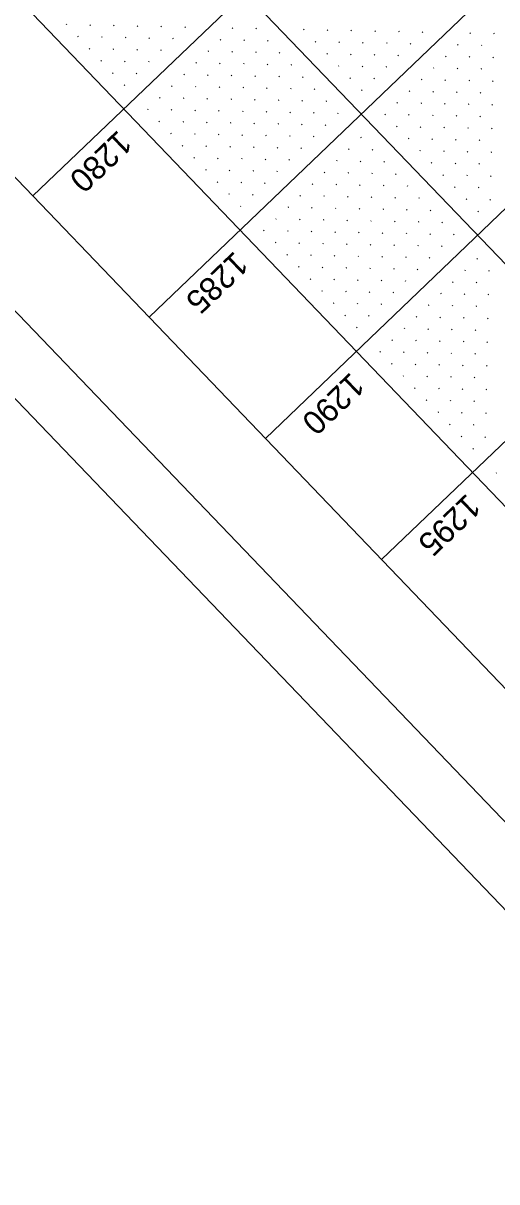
# Model space of a CAD drawing. Extents: x 2148987 to 2151117, y 142806 to 144993.
# Drawn here: x 2149225.7 to 2149366.7, y 143192.6 to 143537.7 of the extents above; entities that cross this region are included whole.
import ezdxf

# ---------------------------------------------------------------- set-up
doc = ezdxf.new("R2010")
doc.units = 0
for name, color, linetype in [('BASELINE', 7, 'Continuous'), ('PR_ABUT_PH3', 7, 'Continuous'), ('PR_PIER_PH3', 7, 'Continuous'), ('PR_Road_Concrete', 7, 'Continuous'), ('SHT_Profile_Grid_Minor', 7, 'Continuous'), ('Wall D Bore', 7, 'Continuous')]:
    doc.layers.add(name, color=color, linetype=linetype)

msp = doc.modelspace()

# ---------------------------------------------------------------- linework, layer by layer
at = {"layer": 'BASELINE'}
msp.add_lwpolyline([(2151029.45, 144024.32), (2149802.07, 142848.08), (2149040.98, 143642.27), (2150268.36, 144818.51)], close=True, dxfattribs=at)
at = {"layer": 'PR_ABUT_PH3'}
msp.add_lwpolyline([(2151117.11, 144051.19), (2149817.52, 142805.76), (2148987.24, 143672.15), (2150286.82, 144917.58)], close=True, dxfattribs=at)
at = {"layer": 'PR_PIER_PH3'}
for p, q in [((2150365.75, 144575.97), (2149228.62, 143486.22)), ((2150400.35, 144539.87), (2149263.21, 143450.12)), ((2150434.94, 144503.77), (2149297.81, 143414.02)), ((2150469.54, 144467.67), (2149332.4, 143377.92)), ((2149222.6, 143618.96), (2149468.23, 143362.65))]:
    msp.add_line(p, q, dxfattribs=at)
at = {"layer": 'PR_Road_Concrete'}
msp.add_line((2149134.61, 143638.51), (2149463.26, 143295.57), dxfattribs=at)
msp.add_lwpolyline([(2150941.76, 143974.91), (2149804.63, 142885.16), (2149078.13, 143643.25), (2150215.26, 144733)], close=True, dxfattribs=at)
at = {"layer": 'SHT_Profile_Grid_Minor'}
for p, q in [((2149238.64, 143537.37), (2149238.45, 143537.2)), ((2149245.7, 143537.22), (2149245.52, 143537.05)), ((2149252.77, 143537.07), (2149252.59, 143536.9)), ((2149259.84, 143536.92), (2149259.66, 143536.75)), ((2149266.91, 143536.77), (2149266.73, 143536.6)), ((2149273.98, 143536.62), (2149273.8, 143536.45)), ((2149288.12, 143536.32), (2149287.94, 143536.14)), ((2149295.19, 143536.17), (2149295.01, 143535.99)), ((2149309.33, 143535.87), (2149309.15, 143535.69)), ((2149316.4, 143535.72), (2149316.22, 143535.54)), ((2149323.47, 143535.57), (2149323.29, 143535.39)), ((2149330.54, 143535.41), (2149330.36, 143535.24)), ((2149337.61, 143535.26), (2149337.43, 143535.09)), ((2149344.68, 143535.11), (2149344.5, 143534.94)), ((2149358.82, 143534.81), (2149358.64, 143534.64)), ((2149365.89, 143534.66), (2149365.71, 143534.49)), ((2149242.09, 143533.76), (2149241.91, 143533.59)), ((2149249.16, 143533.61), (2149248.98, 143533.44)), ((2149256.23, 143533.46), (2149256.05, 143533.29)), ((2149263.3, 143533.31), (2149263.12, 143533.14)), ((2149270.37, 143533.16), (2149270.19, 143532.99)), ((2149284.51, 143532.86), (2149284.33, 143532.68)), ((2149291.58, 143532.71), (2149291.4, 143532.53)), ((2149298.65, 143532.56), (2149298.47, 143532.38)), ((2149312.79, 143532.26), (2149312.61, 143532.08)), ((2149319.86, 143532.11), (2149319.68, 143531.93)), ((2149326.93, 143531.96), (2149326.75, 143531.78)), ((2149334, 143531.8), (2149333.82, 143531.63)), ((2149341.07, 143531.65), (2149340.89, 143531.48)), ((2149355.21, 143531.35), (2149355.03, 143531.18)), ((2149362.28, 143531.2), (2149362.1, 143531.03)), ((2149245.55, 143530.15), (2149245.37, 143529.98)), ((2149252.62, 143530), (2149252.44, 143529.83)), ((2149259.69, 143529.85), (2149259.51, 143529.68)), ((2149266.76, 143529.7), (2149266.58, 143529.53)), ((2149280.9, 143529.4), (2149280.72, 143529.23)), ((2149287.97, 143529.25), (2149287.79, 143529.07)), ((2149295.04, 143529.1), (2149294.86, 143528.92)), ((2149302.11, 143528.95), (2149301.93, 143528.77)), ((2149316.25, 143528.65), (2149316.07, 143528.47)), ((2149323.32, 143528.5), (2149323.14, 143528.32)), ((2149330.39, 143528.35), (2149330.21, 143528.17)), ((2149337.46, 143528.19), (2149337.28, 143528.02)), ((2149351.6, 143527.89), (2149351.42, 143527.72)), ((2149358.67, 143527.74), (2149358.49, 143527.57)), ((2149365.74, 143527.59), (2149365.55, 143527.42)), ((2149249.01, 143526.54), (2149248.83, 143526.37)), ((2149256.08, 143526.39), (2149255.9, 143526.22)), ((2149263.15, 143526.24), (2149262.97, 143526.07)), ((2149277.29, 143525.94), (2149277.11, 143525.77)), ((2149284.36, 143525.79), (2149284.18, 143525.62)), ((2149291.43, 143525.64), (2149291.25, 143525.46)), ((2149298.5, 143525.49), (2149298.32, 143525.31)), ((2149305.57, 143525.34), (2149305.39, 143525.16)), ((2149319.71, 143525.04), (2149319.53, 143524.86)), ((2149326.78, 143524.89), (2149326.6, 143524.71)), ((2149333.85, 143524.74), (2149333.67, 143524.56)), ((2149347.99, 143524.43), (2149347.81, 143524.26)), ((2149355.06, 143524.28), (2149354.88, 143524.11)), ((2149362.13, 143524.13), (2149361.94, 143523.96)), ((2149252.47, 143522.93), (2149252.29, 143522.76)), ((2149259.54, 143522.78), (2149259.36, 143522.61)), ((2149273.68, 143522.48), (2149273.5, 143522.31)), ((2149280.75, 143522.33), (2149280.57, 143522.16)), ((2149287.82, 143522.18), (2149287.64, 143522.01)), ((2149294.89, 143522.03), (2149294.71, 143521.86)), ((2149301.96, 143521.88), (2149301.78, 143521.7)), ((2149309.03, 143521.73), (2149308.85, 143521.55)), ((2149323.17, 143521.43), (2149322.99, 143521.25)), ((2149330.24, 143521.28), (2149330.06, 143521.1)), ((2149344.38, 143520.97), (2149344.2, 143520.8)), ((2149351.45, 143520.82), (2149351.27, 143520.65)), ((2149358.52, 143520.67), (2149358.33, 143520.5)), ((2149365.58, 143520.52), (2149365.4, 143520.35)), ((2149255.93, 143519.32), (2149255.75, 143519.15)), ((2149270.07, 143519.02), (2149269.89, 143518.85)), ((2149277.14, 143518.87), (2149276.96, 143518.7)), ((2149284.21, 143518.72), (2149284.03, 143518.55)), ((2149291.28, 143518.57), (2149291.1, 143518.4)), ((2149298.35, 143518.42), (2149298.17, 143518.25)), ((2149305.42, 143518.27), (2149305.24, 143518.09)), ((2149312.49, 143518.12), (2149312.31, 143517.94)), ((2149326.63, 143517.82), (2149326.45, 143517.64)), ((2149340.77, 143517.52), (2149340.59, 143517.34)), ((2149347.84, 143517.36), (2149347.66, 143517.19)), ((2149354.91, 143517.21), (2149354.72, 143517.04)), ((2149361.97, 143517.06), (2149361.79, 143516.89)), ((2149266.46, 143515.56), (2149266.28, 143515.39)), ((2149273.53, 143515.41), (2149273.35, 143515.24)), ((2149280.6, 143515.26), (2149280.42, 143515.09)), ((2149287.67, 143515.11), (2149287.49, 143514.94)), ((2149294.74, 143514.96), (2149294.56, 143514.79)), ((2149301.81, 143514.81), (2149301.63, 143514.64)), ((2149308.88, 143514.66), (2149308.7, 143514.48)), ((2149315.95, 143514.51), (2149315.77, 143514.33)), ((2149337.16, 143514.06), (2149336.98, 143513.88)), ((2149344.23, 143513.91), (2149344.05, 143513.73)), ((2149351.3, 143513.76), (2149351.12, 143513.58)), ((2149358.36, 143513.6), (2149358.18, 143513.43)), ((2149262.85, 143512.1), (2149262.67, 143511.93)), ((2149269.92, 143511.95), (2149269.74, 143511.78)), ((2149276.99, 143511.8), (2149276.81, 143511.63)), ((2149284.06, 143511.65), (2149283.88, 143511.48)), ((2149291.13, 143511.5), (2149290.95, 143511.33)), ((2149298.2, 143511.35), (2149298.02, 143511.18)), ((2149305.27, 143511.2), (2149305.09, 143511.03)), ((2149312.34, 143511.05), (2149312.16, 143510.87)), ((2149319.41, 143510.9), (2149319.23, 143510.72)), ((2149333.55, 143510.6), (2149333.37, 143510.42)), ((2149340.62, 143510.45), (2149340.44, 143510.27)), ((2149347.69, 143510.3), (2149347.51, 143510.12)), ((2149365.43, 143513.45), (2149365.25, 143513.28)), ((2149266.31, 143508.49), (2149266.13, 143508.32)), ((2149273.38, 143508.34), (2149273.2, 143508.17)), ((2149280.45, 143508.19), (2149280.27, 143508.02)), ((2149287.52, 143508.04), (2149287.34, 143507.87)), ((2149294.59, 143507.89), (2149294.41, 143507.72)), ((2149301.66, 143507.74), (2149301.48, 143507.57)), ((2149308.73, 143507.59), (2149308.55, 143507.42)), ((2149315.8, 143507.44), (2149315.62, 143507.26)), ((2149337.01, 143506.99), (2149336.83, 143506.81)), ((2149344.08, 143506.84), (2149343.9, 143506.66)), ((2149354.76, 143510.15), (2149354.57, 143509.97)), ((2149361.82, 143509.99), (2149361.64, 143509.82)), ((2149269.77, 143504.88), (2149269.59, 143504.71)), ((2149276.84, 143504.73), (2149276.66, 143504.56)), ((2149283.91, 143504.58), (2149283.73, 143504.41)), ((2149290.98, 143504.43), (2149290.8, 143504.26)), ((2149298.05, 143504.28), (2149297.87, 143504.11)), ((2149305.12, 143504.13), (2149304.94, 143503.96)), ((2149312.19, 143503.98), (2149312.01, 143503.81)), ((2149326.33, 143503.68), (2149326.15, 143503.5)), ((2149340.47, 143503.38), (2149340.29, 143503.2)), ((2149351.15, 143506.69), (2149350.96, 143506.51)), ((2149358.21, 143506.54), (2149358.03, 143506.36)), ((2149365.28, 143506.38), (2149365.1, 143506.21)), ((2149273.23, 143501.27), (2149273.05, 143501.1)), ((2149280.3, 143501.12), (2149280.12, 143500.95)), ((2149287.37, 143500.97), (2149287.19, 143500.8)), ((2149294.44, 143500.82), (2149294.26, 143500.65)), ((2149301.51, 143500.67), (2149301.33, 143500.5)), ((2149308.58, 143500.52), (2149308.4, 143500.35)), ((2149322.72, 143500.22), (2149322.54, 143500.04)), ((2149329.79, 143500.07), (2149329.61, 143499.89)), ((2149347.54, 143503.23), (2149347.35, 143503.05)), ((2149354.6, 143503.08), (2149354.42, 143502.9)), ((2149361.67, 143502.93), (2149361.49, 143502.75)), ((2149276.69, 143497.66), (2149276.51, 143497.49)), ((2149283.76, 143497.51), (2149283.58, 143497.34)), ((2149290.83, 143497.36), (2149290.65, 143497.19)), ((2149297.9, 143497.21), (2149297.72, 143497.04)), ((2149304.97, 143497.06), (2149304.79, 143496.89)), ((2149319.11, 143496.76), (2149318.93, 143496.59)), ((2149326.18, 143496.61), (2149326, 143496.43)), ((2149333.25, 143496.46), (2149333.07, 143496.28)), ((2149343.93, 143499.77), (2149343.74, 143499.59)), ((2149350.99, 143499.62), (2149350.81, 143499.44)), ((2149358.06, 143499.47), (2149357.88, 143499.29)), ((2149365.13, 143499.32), (2149364.95, 143499.14)), ((2149280.15, 143494.05), (2149279.97, 143493.88)), ((2149287.22, 143493.9), (2149287.04, 143493.73)), ((2149294.29, 143493.75), (2149294.11, 143493.58)), ((2149301.36, 143493.6), (2149301.18, 143493.43)), ((2149315.5, 143493.3), (2149315.32, 143493.13)), ((2149322.57, 143493.15), (2149322.39, 143492.98)), ((2149329.64, 143493), (2149329.46, 143492.82)), ((2149347.38, 143496.16), (2149347.2, 143495.98)), ((2149354.45, 143496.01), (2149354.27, 143495.83)), ((2149361.52, 143495.86), (2149361.34, 143495.68)), ((2149283.61, 143490.44), (2149283.43, 143490.27)), ((2149290.68, 143490.29), (2149290.5, 143490.12)), ((2149297.75, 143490.14), (2149297.57, 143489.97)), ((2149311.89, 143489.84), (2149311.71, 143489.67)), ((2149318.96, 143489.69), (2149318.78, 143489.52)), ((2149326.03, 143489.54), (2149325.85, 143489.37)), ((2149336.71, 143492.85), (2149336.52, 143492.67)), ((2149350.84, 143492.55), (2149350.66, 143492.37)), ((2149357.91, 143492.4), (2149357.73, 143492.22)), ((2149364.98, 143492.25), (2149364.8, 143492.07)), ((2149287.07, 143486.83), (2149286.89, 143486.66)), ((2149294.14, 143486.68), (2149293.96, 143486.51)), ((2149308.28, 143486.38), (2149308.1, 143486.21)), ((2149315.35, 143486.23), (2149315.17, 143486.06)), ((2149322.42, 143486.08), (2149322.24, 143485.91)), ((2149333.1, 143489.39), (2149332.91, 143489.22)), ((2149340.16, 143489.24), (2149339.98, 143489.06)), ((2149354.3, 143488.94), (2149354.12, 143488.76)), ((2149361.37, 143488.79), (2149361.19, 143488.61)), ((2149290.53, 143483.22), (2149290.35, 143483.05)), ((2149304.67, 143482.92), (2149304.49, 143482.75)), ((2149311.74, 143482.77), (2149311.56, 143482.6)), ((2149318.81, 143482.62), (2149318.63, 143482.45)), ((2149329.49, 143485.93), (2149329.3, 143485.76)), ((2149336.55, 143485.78), (2149336.37, 143485.61)), ((2149343.62, 143485.63), (2149343.44, 143485.45)), ((2149357.76, 143485.33), (2149357.58, 143485.15)), ((2149364.83, 143485.18), (2149364.65, 143485)), ((2149301.06, 143479.46), (2149300.88, 143479.29)), ((2149308.13, 143479.31), (2149307.95, 143479.14)), ((2149315.2, 143479.16), (2149315.02, 143478.99)), ((2149325.88, 143482.47), (2149325.69, 143482.3)), ((2149332.94, 143482.32), (2149332.76, 143482.15)), ((2149340.01, 143482.17), (2149339.83, 143482)), ((2149347.08, 143482.02), (2149346.9, 143481.84)), ((2149361.22, 143481.72), (2149361.04, 143481.54)), ((2149297.45, 143476), (2149297.27, 143475.83)), ((2149304.52, 143475.85), (2149304.34, 143475.68)), ((2149311.59, 143475.7), (2149311.41, 143475.53)), ((2149322.27, 143479.01), (2149322.08, 143478.84)), ((2149329.33, 143478.86), (2149329.15, 143478.69)), ((2149336.4, 143478.71), (2149336.22, 143478.54)), ((2149343.47, 143478.56), (2149343.29, 143478.39)), ((2149350.54, 143478.41), (2149350.36, 143478.23)), ((2149300.91, 143472.39), (2149300.73, 143472.22)), ((2149307.98, 143472.24), (2149307.8, 143472.07)), ((2149318.66, 143475.55), (2149318.48, 143475.38)), ((2149325.72, 143475.4), (2149325.54, 143475.23)), ((2149332.79, 143475.25), (2149332.61, 143475.08)), ((2149339.86, 143475.1), (2149339.68, 143474.93)), ((2149346.93, 143474.95), (2149346.75, 143474.78)), ((2149354, 143474.8), (2149353.82, 143474.62)), ((2149304.37, 143468.78), (2149304.19, 143468.61)), ((2149315.05, 143472.09), (2149314.87, 143471.92)), ((2149322.12, 143471.94), (2149321.93, 143471.77)), ((2149329.18, 143471.79), (2149329, 143471.62)), ((2149336.25, 143471.64), (2149336.07, 143471.47)), ((2149343.32, 143471.49), (2149343.14, 143471.32)), ((2149350.39, 143471.34), (2149350.21, 143471.17)), ((2149311.44, 143468.63), (2149311.26, 143468.46)), ((2149318.51, 143468.48), (2149318.32, 143468.31)), ((2149325.57, 143468.33), (2149325.39, 143468.16)), ((2149332.64, 143468.18), (2149332.46, 143468.01)), ((2149339.71, 143468.03), (2149339.53, 143467.86)), ((2149346.78, 143467.88), (2149346.6, 143467.71)), ((2149360.92, 143467.58), (2149360.74, 143467.4)), ((2149307.83, 143465.17), (2149307.65, 143465)), ((2149314.9, 143465.02), (2149314.71, 143464.85)), ((2149321.96, 143464.87), (2149321.78, 143464.7)), ((2149329.03, 143464.72), (2149328.85, 143464.55)), ((2149336.1, 143464.57), (2149335.92, 143464.4)), ((2149343.17, 143464.42), (2149342.99, 143464.25)), ((2149357.31, 143464.12), (2149357.13, 143463.95)), ((2149364.38, 143463.97), (2149364.2, 143463.79)), ((2149311.29, 143461.56), (2149311.1, 143461.39)), ((2149318.35, 143461.41), (2149318.17, 143461.24)), ((2149325.42, 143461.26), (2149325.24, 143461.09)), ((2149332.49, 143461.11), (2149332.31, 143460.94)), ((2149339.56, 143460.96), (2149339.38, 143460.79)), ((2149353.7, 143460.66), (2149353.52, 143460.49)), ((2149360.77, 143460.51), (2149360.59, 143460.34)), ((2149314.74, 143457.95), (2149314.56, 143457.78)), ((2149321.81, 143457.8), (2149321.63, 143457.63)), ((2149328.88, 143457.65), (2149328.7, 143457.48)), ((2149335.95, 143457.5), (2149335.77, 143457.33)), ((2149350.09, 143457.2), (2149349.91, 143457.03)), ((2149357.16, 143457.05), (2149356.98, 143456.88)), ((2149364.23, 143456.9), (2149364.05, 143456.73)), ((2149318.2, 143454.34), (2149318.02, 143454.17)), ((2149325.27, 143454.19), (2149325.09, 143454.02)), ((2149332.34, 143454.04), (2149332.16, 143453.87)), ((2149346.48, 143453.74), (2149346.3, 143453.57)), ((2149353.55, 143453.59), (2149353.37, 143453.42)), ((2149360.62, 143453.44), (2149360.44, 143453.27)), ((2149321.66, 143450.73), (2149321.48, 143450.56)), ((2149328.73, 143450.58), (2149328.55, 143450.41)), ((2149342.87, 143450.28), (2149342.69, 143450.11)), ((2149349.94, 143450.13), (2149349.76, 143449.96)), ((2149357.01, 143449.98), (2149356.83, 143449.81)), ((2149364.08, 143449.83), (2149363.9, 143449.66)), ((2149325.12, 143447.12), (2149324.94, 143446.95)), ((2149339.26, 143446.82), (2149339.08, 143446.65)), ((2149346.33, 143446.67), (2149346.15, 143446.5)), ((2149353.4, 143446.52), (2149353.22, 143446.35)), ((2149360.47, 143446.37), (2149360.29, 143446.2)), ((2149335.65, 143443.36), (2149335.47, 143443.19)), ((2149342.72, 143443.21), (2149342.54, 143443.04)), ((2149349.79, 143443.06), (2149349.61, 143442.89)), ((2149356.86, 143442.91), (2149356.68, 143442.74)), ((2149363.93, 143442.76), (2149363.75, 143442.59)), ((2149332.04, 143439.9), (2149331.86, 143439.73)), ((2149339.11, 143439.75), (2149338.93, 143439.58)), ((2149346.18, 143439.6), (2149346, 143439.43)), ((2149353.25, 143439.45), (2149353.07, 143439.28)), ((2149360.32, 143439.3), (2149360.14, 143439.13)), ((2149335.5, 143436.29), (2149335.32, 143436.12)), ((2149342.57, 143436.14), (2149342.39, 143435.97)), ((2149349.64, 143435.99), (2149349.46, 143435.82)), ((2149356.71, 143435.84), (2149356.53, 143435.67)), ((2149363.78, 143435.69), (2149363.6, 143435.52)), ((2149338.96, 143432.68), (2149338.78, 143432.51)), ((2149346.03, 143432.53), (2149345.85, 143432.36)), ((2149353.1, 143432.38), (2149352.92, 143432.21)), ((2149360.17, 143432.23), (2149359.99, 143432.06)), ((2149342.42, 143429.07), (2149342.24, 143428.9)), ((2149349.49, 143428.92), (2149349.31, 143428.75)), ((2149356.56, 143428.77), (2149356.38, 143428.6)), ((2149363.63, 143428.62), (2149363.45, 143428.45)), ((2149345.88, 143425.46), (2149345.7, 143425.29)), ((2149352.95, 143425.31), (2149352.77, 143425.14)), ((2149360.02, 143425.16), (2149359.84, 143424.99)), ((2149349.34, 143421.85), (2149349.16, 143421.68)), ((2149356.41, 143421.7), (2149356.23, 143421.53)), ((2149363.48, 143421.55), (2149363.3, 143421.38)), ((2149352.8, 143418.24), (2149352.62, 143418.07)), ((2149359.87, 143418.09), (2149359.69, 143417.92)), ((2149356.26, 143414.63), (2149356.08, 143414.46)), ((2149363.33, 143414.48), (2149363.15, 143414.31)), ((2149359.72, 143411.02), (2149359.54, 143410.85)), ((2149366.64, 143403.8), (2149366.46, 143403.63))]:
    msp.add_line(p, q, dxfattribs=at)

# ---------------------------------------------------------------- texts
at = {"layer": 'Wall D Bore'}
for s, p in [('1280', (2149253.98, 143506.15)), ('1285', (2149288.58, 143470.05)), ('1290', (2149323.17, 143433.95)), ('1295', (2149357.77, 143397.85))]:
    msp.add_text(s, height=7, rotation=223.7809, dxfattribs=at).set_placement(p)

doc.saveas('drawing.dxf')
